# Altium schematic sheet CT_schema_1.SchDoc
size 656 x 443 mm
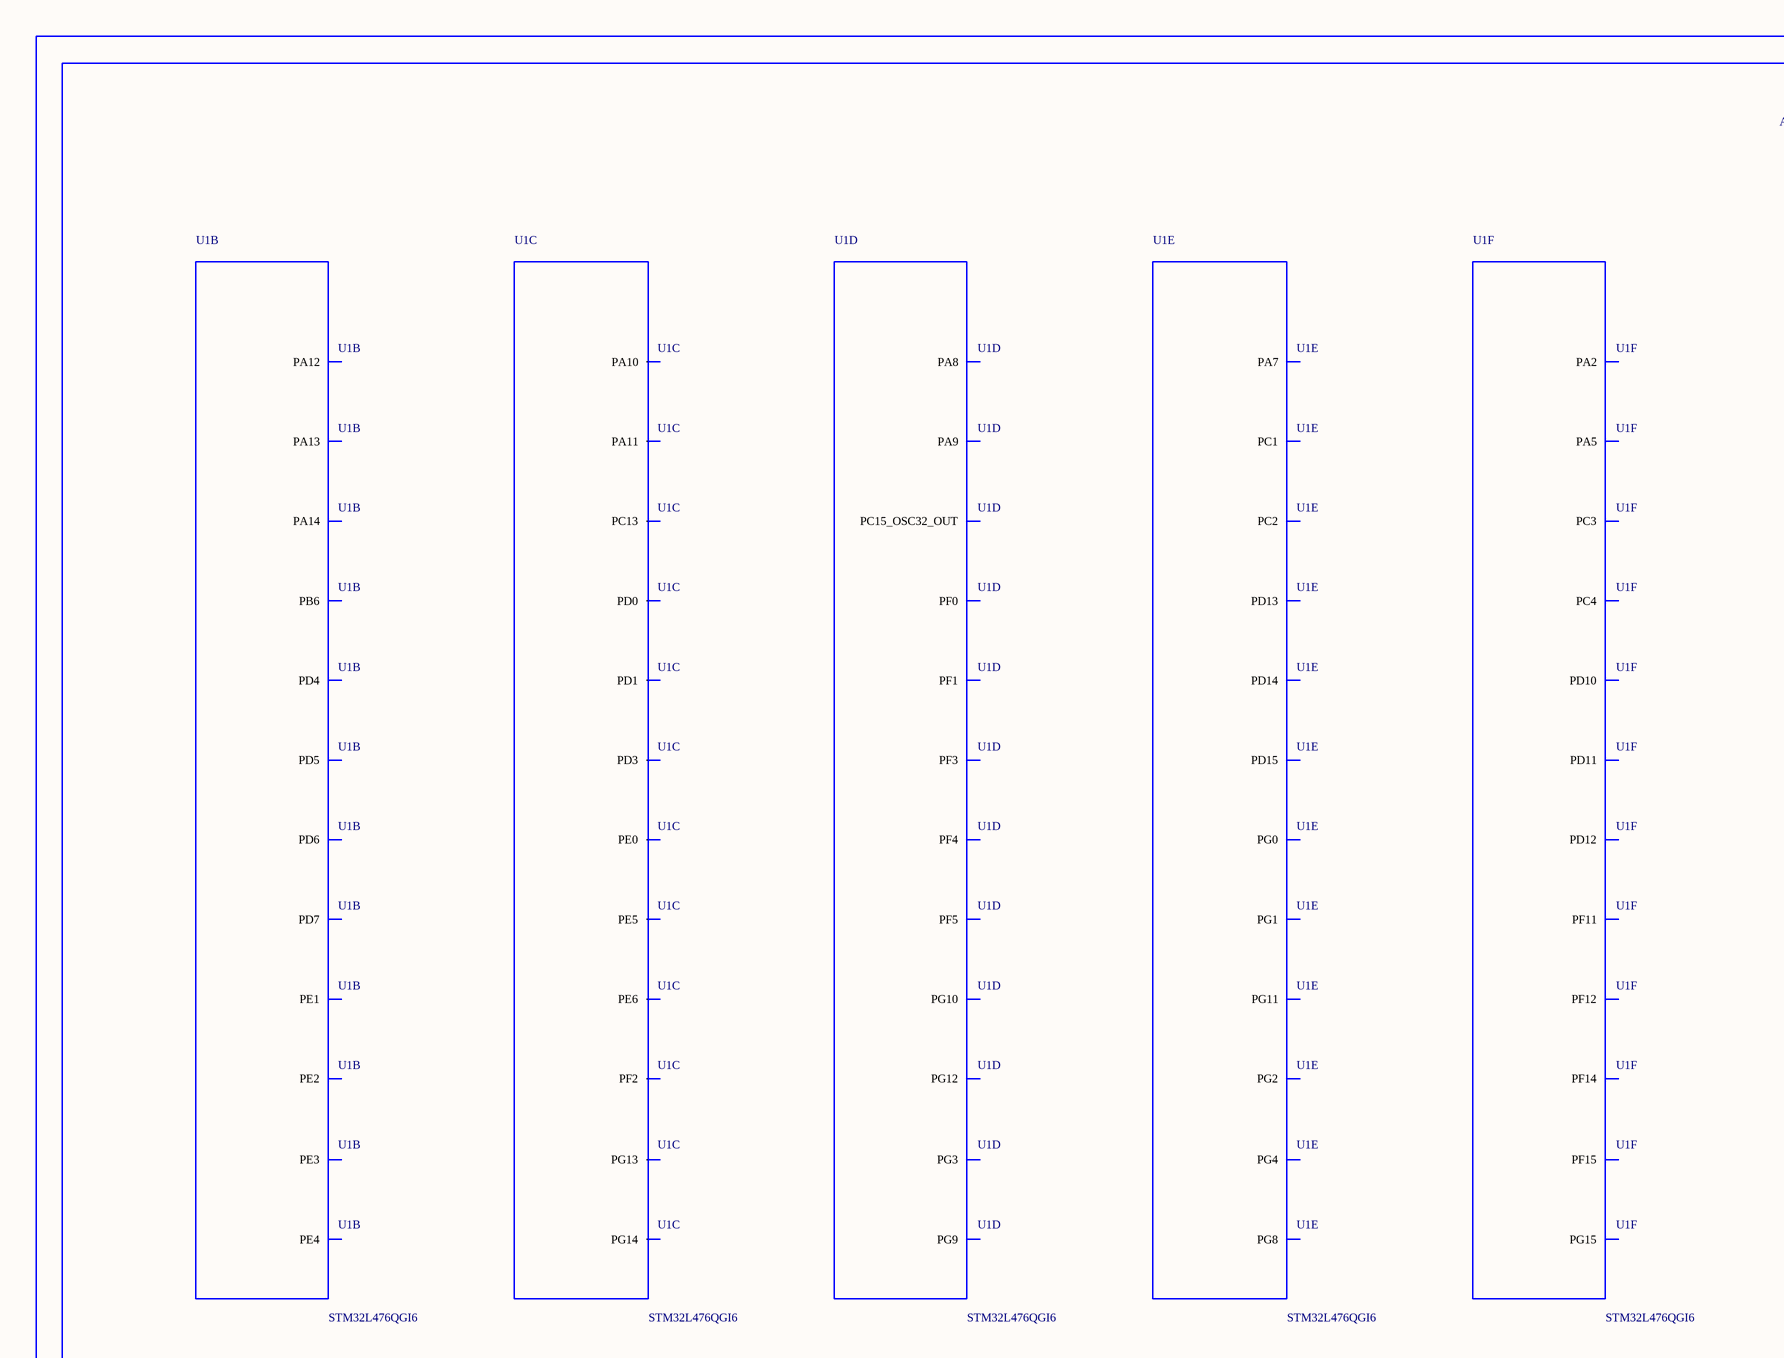
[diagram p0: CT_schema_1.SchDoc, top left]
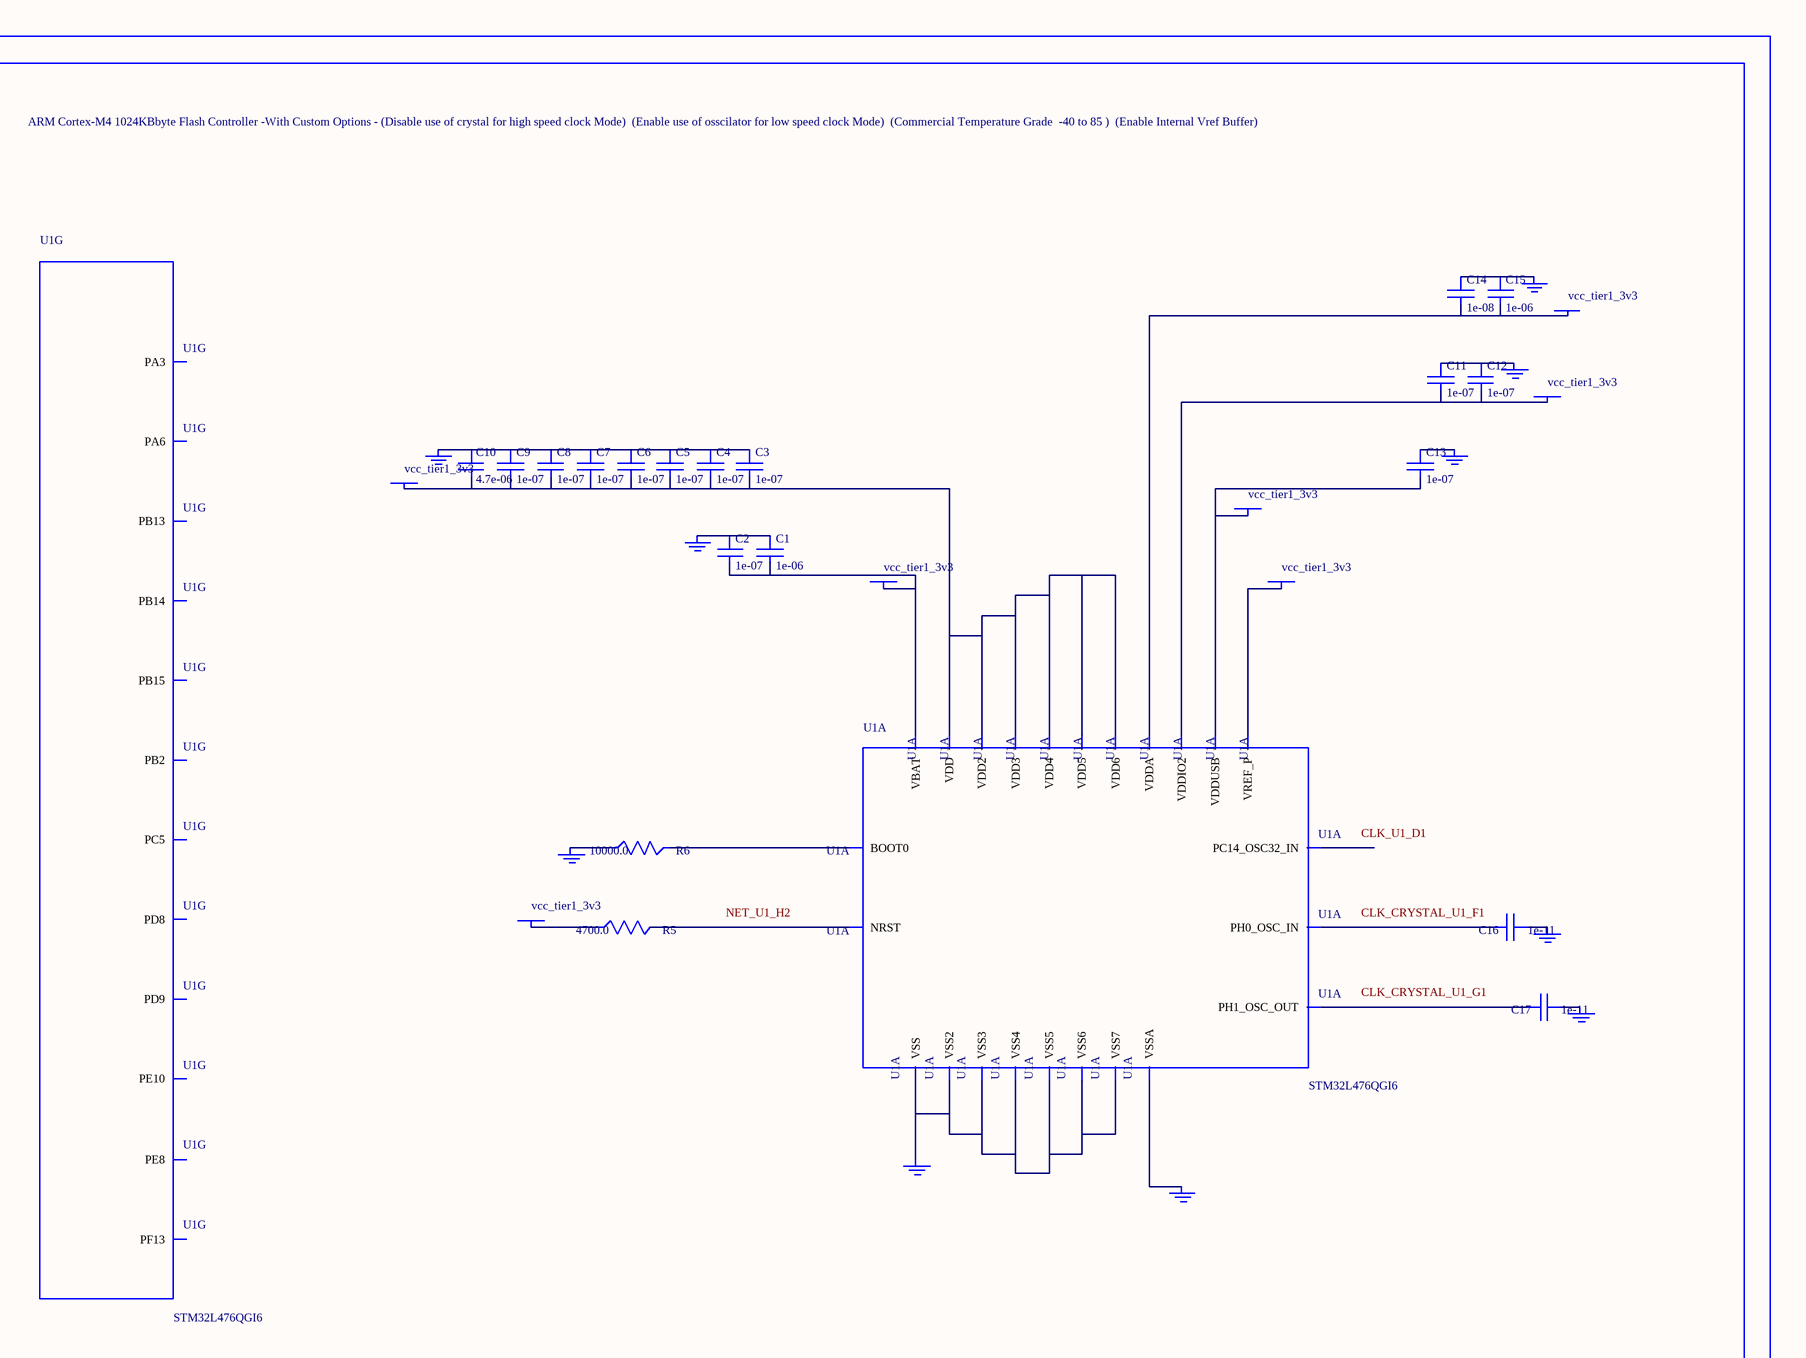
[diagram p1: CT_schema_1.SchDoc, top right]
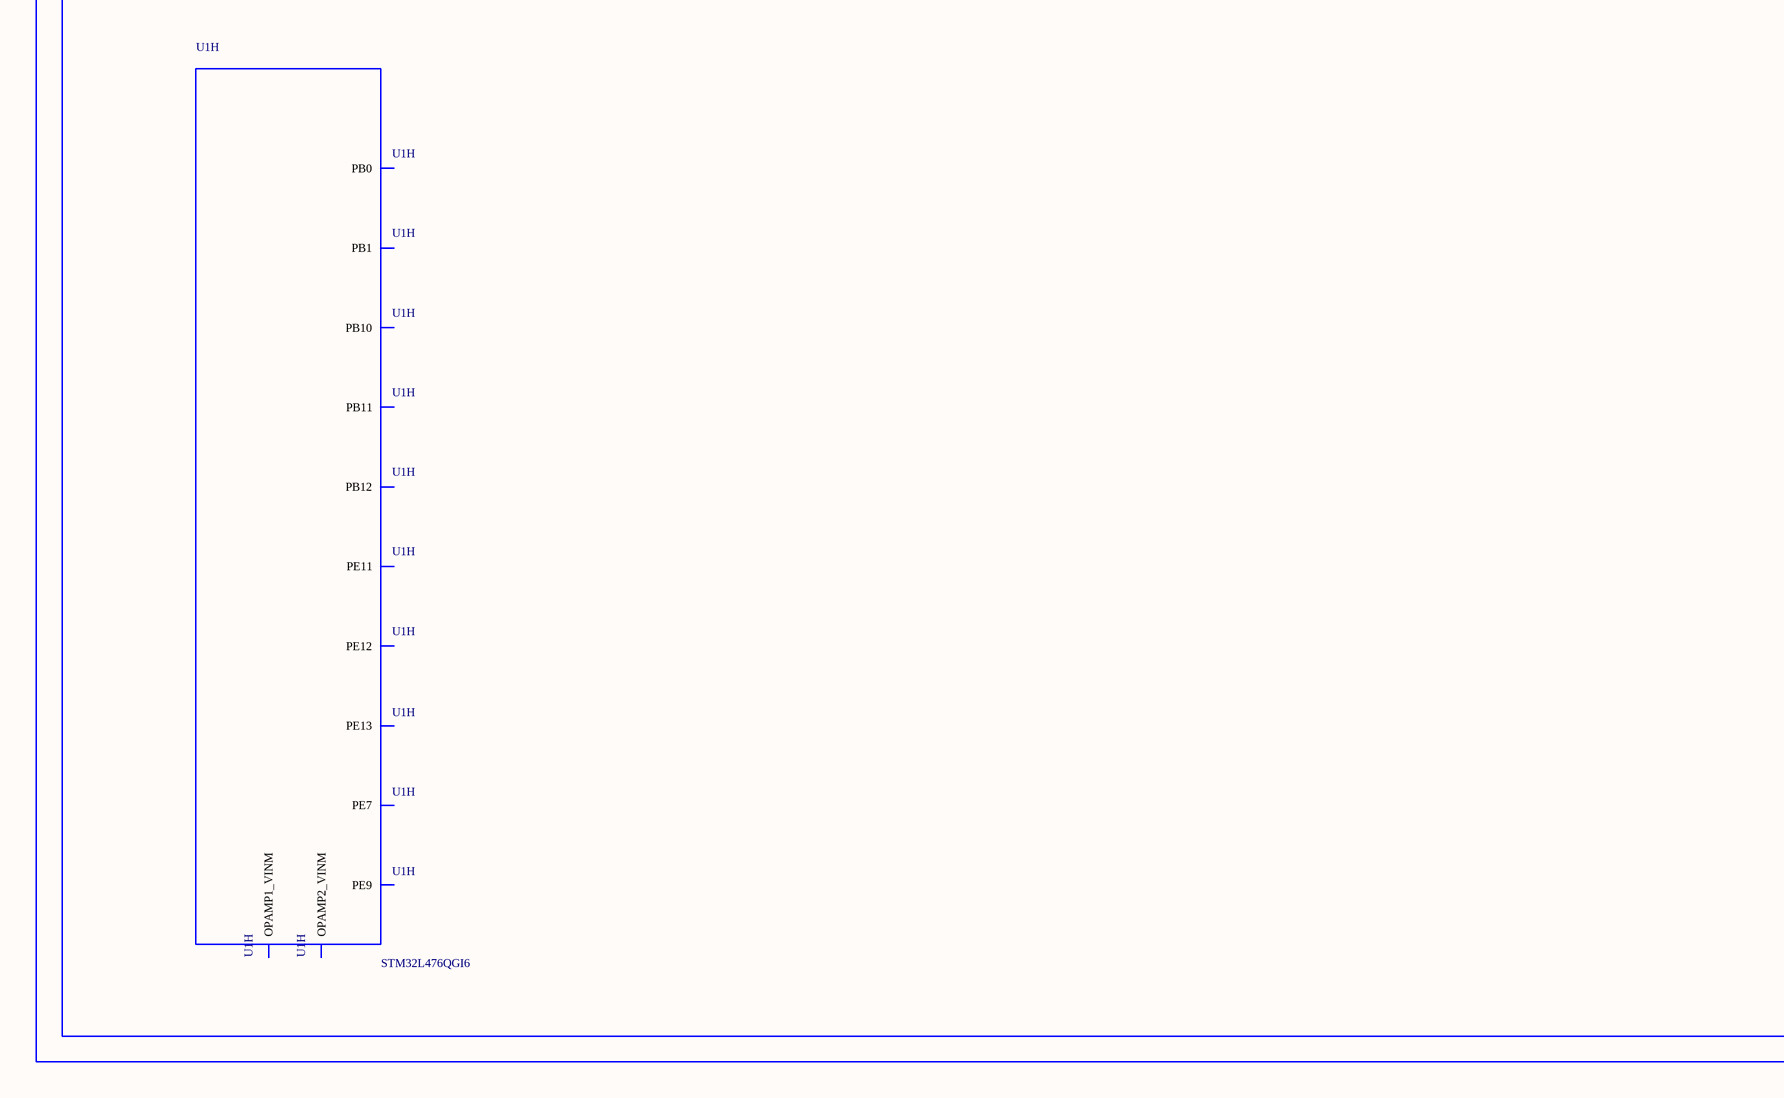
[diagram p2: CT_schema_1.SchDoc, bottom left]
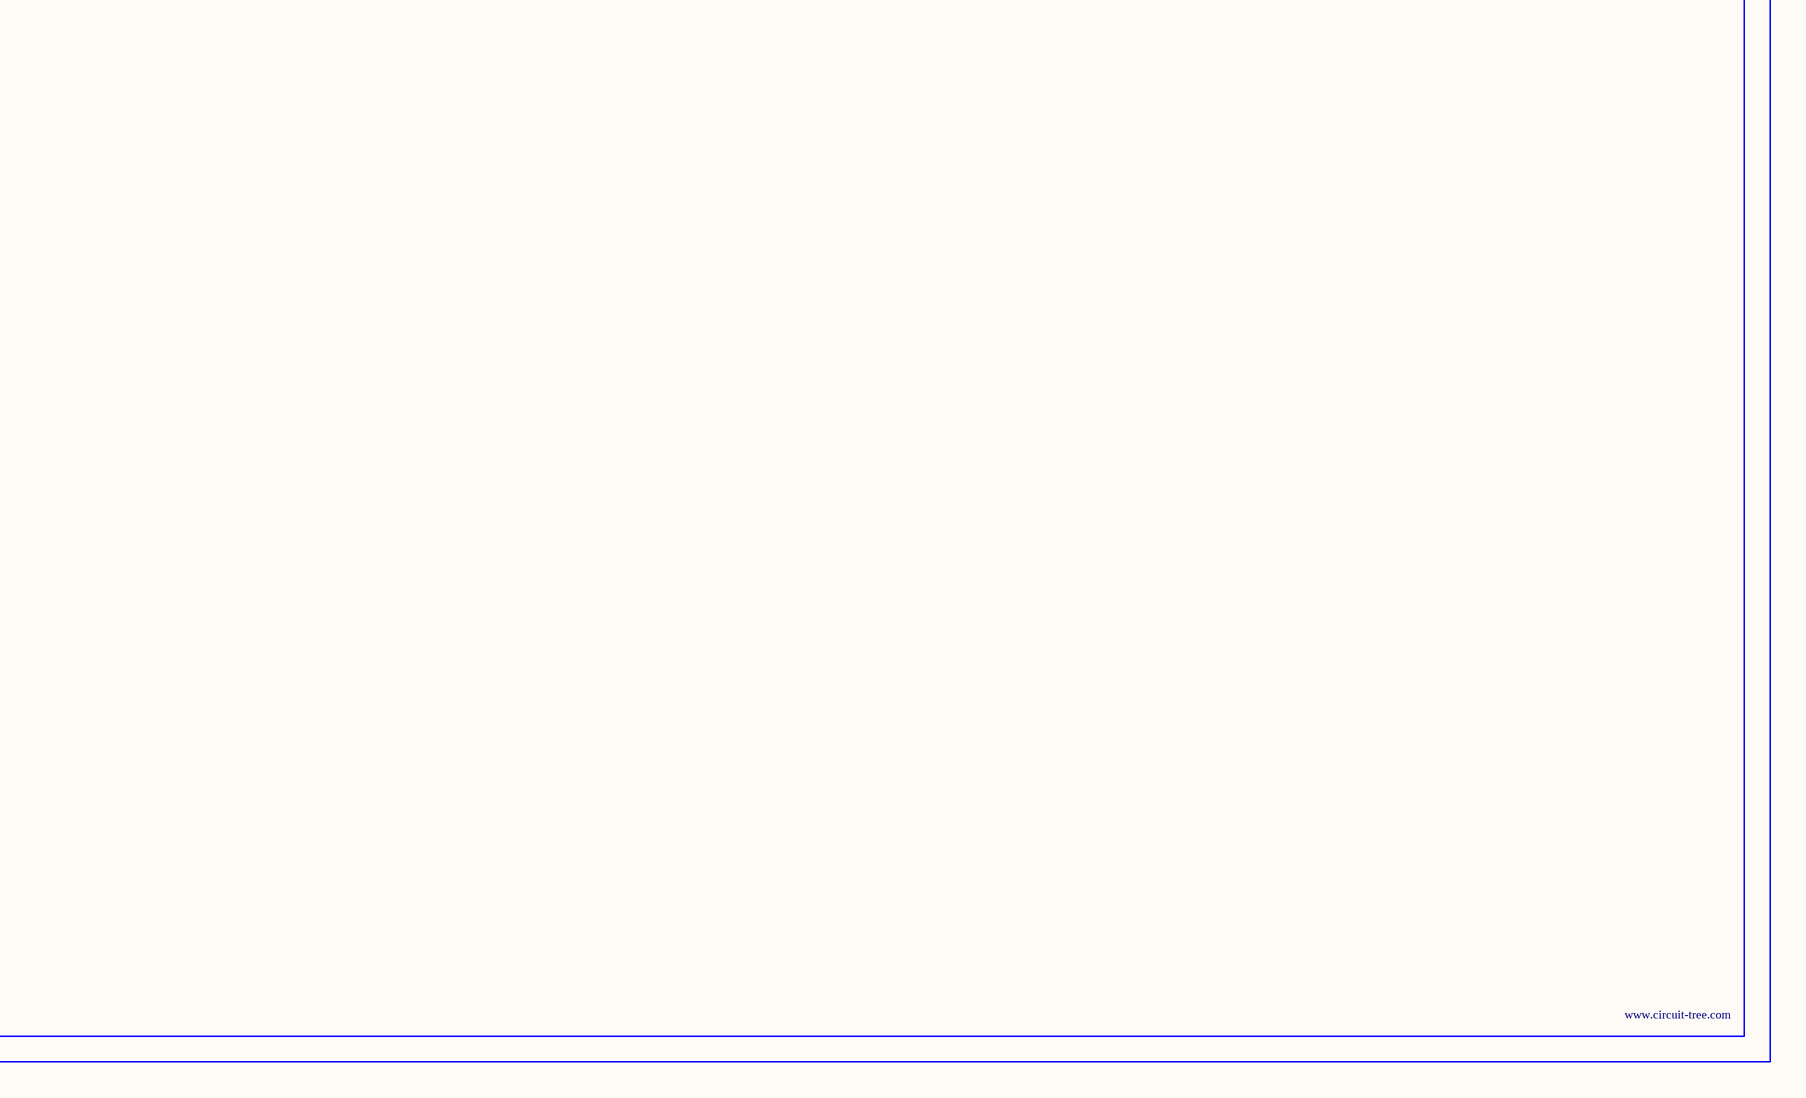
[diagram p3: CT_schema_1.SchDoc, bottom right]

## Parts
BORDER0  (no value)
C1  1e-06  [C0603]
C2  1e-07  [C0603]
C3  1e-07  [C0603]
C4  1e-07  [C0603]
C5  1e-07  [C0603]
C6  1e-07  [C0603]
C7  1e-07  [C0603]
C8  1e-07  [C0603]
C9  1e-07  [C0603]
C10  4.7e-06  [C0603]
C11  1e-07  [C0603]
C12  1e-07  [C0603]
C13  1e-07  [C0603]
C14  1e-08  [C0603]
C15  1e-06  [C0603]
C16  1e-11  [C0402]
C17  1e-11  [C0402]
GND_INSTANCE_0_0  (no value)
GND_INSTANCE_0_1  (no value)
GND_INSTANCE_0_2  (no value)
GND_INSTANCE_0_3  (no value)
GND_INSTANCE_0_4  (no value)
GND_INSTANCE_0_5  (no value)
GND_INSTANCE_0_6  (no value)
GND_INSTANCE_0_7  (no value)
GND_INSTANCE_0_8  (no value)
GND_INSTANCE_0_9  (no value)
POWER_INSTANCE_0_0  vcc_tier1_3v3
POWER_INSTANCE_0_1  vcc_tier1_3v3
POWER_INSTANCE_0_2  vcc_tier1_3v3
POWER_INSTANCE_0_3  vcc_tier1_3v3
POWER_INSTANCE_0_4  vcc_tier1_3v3
POWER_INSTANCE_0_5  vcc_tier1_3v3
POWER_INSTANCE_0_6  vcc_tier1_3v3
R5  4700.0  [R0603]
R6  10000.0  [R0603]
U1  STM32L476QGI6  [UFBGA132]  (parts A,B,C,D,E,F,G,H of 12)

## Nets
NetC1_1: C1.1 C2.1 GND_INSTANCE_0_0.0(GND)
NetC1_2: C1.2 C2.2 POWER_INSTANCE_0_0.0(PWR) U1.E2(VBAT)
NetC3_1: C3.1 C4.1 C5.1 C6.1 C7.1 C8.1 C9.1 C10.1 GND_INSTANCE_0_1.0(GND)
NetC3_2: C3.2 C4.2 C5.2 C6.2 C7.2 C8.2 C9.2 C10.2 POWER_INSTANCE_0_1.0(PWR) U1.C4(VDD) U1.G2(VDD4) U1.G6(VDD5) U1.G11(VDD2) U1.G12(VDD3) U1.H3(VDD6)
NetC11_1: C11.1 C12.1 GND_INSTANCE_0_2.0(GND)
NetC11_2: C11.2 C12.2 POWER_INSTANCE_0_2.0(PWR) U1.G7(VDDIO2)
NetC13_1: C13.1 GND_INSTANCE_0_4.0(GND)
NetC13_2: C13.2 POWER_INSTANCE_0_3.0(PWR) U1.C11(VDDUSB)
NetC14_1: C14.1 C15.1 GND_INSTANCE_0_5.0(GND)
NetC14_2: C14.2 C15.2 POWER_INSTANCE_0_4.0(PWR) U1.M1(VDDA)
NetC16_1: C16.1 GND_INSTANCE_0_6.0(GND)
NetC16_2: C16.2 U1.F1(PH0_OSC_IN)
NetC17_1: C17.1 GND_INSTANCE_0_7.0(GND)
NetC17_2: C17.2 U1.G1(PH1_OSC_OUT)
NetGND_INSTANCE_0_3_0: GND_INSTANCE_0_3.0(GND) R6.1
NetGND_INSTANCE_0_8_0: GND_INSTANCE_0_8.0(GND) U1.J1(VSSA)
NetGND_INSTANCE_0_9_0: GND_INSTANCE_0_9.0(GND) U1.D3(VSS) U1.E3(VSS2) U1.F2(VSS5) U1.F6(VSS6) U1.F7(VSS7) U1.F11(VSS3) U1.F12(VSS4)
NetPOWER_INSTANCE_0_5_0: POWER_INSTANCE_0_5.0(PWR) U1.L1(VREF_P)
NetPOWER_INSTANCE_0_6_0: POWER_INSTANCE_0_6.0(PWR) R5.1
NetR5_2: R5.2 U1.H2(NRST)
NetR6_2: R6.2 U1.A4(BOOT0)

Not connected (* = marked no-connect by the designer): U1 A1(PE3) A2(PE1) A5(PD7) A6(PD5) A10(PA14) A11(PA13) A12(PA12) B1(PE4) B2(PE2) B5(PB6) B6(PD6) B7(PD4) B8(PD3) B9(PD1) B12(PA11) C1(PC13) C2(PE5) C3(PE0) C6(PG14) C7(PG13) C9(PD0) C12(PA10) D1(PC14_OSC32_IN) D2(PE6) D4(PF2) D5(PF1) D6(PF0) D7(PG12) D8(PG10) D9(PG9) D10(PA9) D11(PA8) E1(PC15_OSC32_OUT) E4(PF3) F3(PF4) F4(PF5) F9(PG3) F10(PG4) G3(PG11) G9(PG1) G10(PG2) H9(PG0) H10(PD15) H11(PD14) H12(PD13) J2(PC1) J3(PC2) J5(PA7) J6(PG8) J7(PF12) J8(PF14) J9(PF15) J10(PD12) J11(PD11) J12(PD10) K1(PG15) K2(PC3) K3(PA2) K4(PA5) K5(PC4) K6(PF11) K7(PF13) K8(PD9) K9(PD8) K10(PB15) K11(PB14) K12(PB13) L3(PA3) L4(PA6) L5(PC5) L6(PB2) L7(PE8) L8(PE10) L9(PE12) L10(PB10) L11(PB11) L12(PB12) M3(OPAMP1_VINM) M4(OPAMP2_VINM) M5(PB0) M6(PB1) M7(PE7) M8(PE9) M9(PE11) M10(PE13)

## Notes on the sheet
- Labels drawn without touching a wire or pin: CLK_CRYSTAL_U1_F1, CLK_CRYSTAL_U1_G1, CLK_U1_D1, NET_U1_H2

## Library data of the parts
BORDER0 = BORDER_PAGE0
C1 C15 = C0603C105K3RACTU
C2-C9 C11-C13 = 06035C104K4Z2A
C10 = GRM188R6YA475KE15D
C14 = 06035C103K4Z2A
C16 C17 = C0402C100K3GACTU
GND_INSTANCE_0_0-GND_INSTANCE_0_9 = GND
POWER_INSTANCE_0_0-POWER_INSTANCE_0_6 = PWR
R5 = RC0603JR-074K7L
R6 = RC0603JR-0710KL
